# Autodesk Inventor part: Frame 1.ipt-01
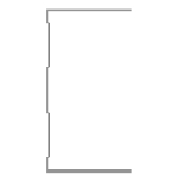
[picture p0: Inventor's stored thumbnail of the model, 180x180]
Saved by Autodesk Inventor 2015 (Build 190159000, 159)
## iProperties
_CCFamilyMember: 1
_CCFamilyDisplayName: Kévin - Kévin Novo
_FrameMemberDoc: Frame Member File
_Version: 15.0.0
_GetPNFromCC: 1
Created: 2015-04
Part Number: Frame 1.ipt-01
Material: Aluminum 6061
Description: Kévin Novo
Document SubType Name: Modeling
Standard: Kevin
Designer: suporte
Standards Organization: Kevin
Language: en-US
Size Designation: (Unnamed 1)
Categories: <MemberInstance><Categories><Category DisplayName="Structural Shapes" InternalName="089c4875-fa83-4c05-b084-43b9cc11f5ed" Mnemonic="GRDR"><CategoryParameter Dis
Density: 2.7 g/cm^3
Appearance: Aluminum - Flat
IsCustomPart: 1
G_L: 1275,000 mm
G_W: 50,000 mm
G_H: 75,000 mm
+97E5C577-A316-488B-9898-4BCBE5543E85+CUTDETAIL1: Cut
+B5E3F3FC-8DAF-4209-9454-317D479D3EF3+CUTDETAIL2: Cut
Author: suporte
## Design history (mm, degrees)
node "Start Plane"
node "End Plane"
sketch "Sketch"
  geometry: L1 (24.7, 37.5)-(24.7, 36.9); L2 (24.7, 36.9)-(-24.7, 36.9); L3 (-24.7, -36.9)-(24.7, -36.9); L4 (24.7, -36.9)-(24.7, -37.5); L5 (24.7, -37.5)-(-25.3, -37.5); L6 (-25.3, 37.5)-(24.7, 37.5); L7 (-24.7, 36.9)-(-24.7, 31.9); L8 (-24.7, 31.9)-(-23.3, 30.5); L9 (-23.3, 30.5)-(-23.3, 10.934); L10 (-23.3, 10.934)-(-24.7, 9.534); L11 (-24.7, 9.534)-(-24.7, -9.534); L12 (-24.7, -9.534)-(-23.3, -10.934); L13 (-23.3, -10.934)-(-23.3, -30.5); L14 (-23.3, -30.5)-(-24.7, -31.9); L15 (-24.7, -31.9)-(-24.7, -36.9); L16 (-25.3, -37.5)-(-25.3, -31.651); L17 (-25.3, -31.651)-(-23.9, -30.251); L18 (-23.9, -30.251)-(-23.9, -11.183); L19 (-23.9, -11.183)-(-25.3, -9.783); L20 (-25.3, -9.783)-(-25.3, 9.783); L21 (-25.3, 9.783)-(-23.9, 11.183); L22 (-23.9, 11.183)-(-23.9, 30.251); L23 (-23.9, 30.251)-(-25.3, 31.651); L24 (-25.3, 31.651)-(-25.3, 37.5); L25 (-25.3, 0)-(30.37, 0); 3 further points
  constraints: 50 end point, 10 point on line, 9 parallel, 5 perpendicular, 4 equal length, 3 midpoint, 3 vertical, 2 vertical alignment, 1 collinear, 1 horizontal, 1 horizontal alignment
  dimensions: "d3" = 0.6 distance of L1.start L1.end (= d6); "d5" = 75 distance between parallel lines of L5 L6; "d6" = 0.6 distance between parallel lines of L24 L7 (= d8); "d7" = 0.6 distance between parallel lines of L8 L23 (= d8); "d8" = 0.6 distance between parallel lines of L22 L9 (= d12); "Espessura" = 0.6 distance between parallel lines of L17 L14; "d10" = 0.6 distance between parallel lines of L13 L18 (= Espessura); "d11" = 0.6 distance between parallel lines of L12 L19 (= Espessura); "d12" = 0.6 distance between parallel lines of L21 L10 (= d11); "d13" = 5 distance of L2.end L7.end; "d15" = 135 deg angle of L9 L8; "d16" = 2 distance between parallel lines of L24 L9; "d17" = 50 distance of L6.start L1.start
extrude "Body" join sketch "Sketch" stored distance "d24" = 0.13; taper "d25" = 0 deg
node "Driven Length"
  sketch "Sketch10"
    geometry: L1 (0, 0)-(10, 0) reference
    constraints: 2 end point, 1 horizontal
  workplane "Work Plane7"
  sketch "Sketch11"
    geometry: L1 (-2, -87.5)-(12, -87.5) reference; L2 (-2, 1187.5)-(12, 1187.5) reference
    dimensions: "d27" = 1275 distance between parallel lines of L1 L2 (derived)
workplane "Work Plane8"
split "Split1"
workplane "Work Plane9"
split "Split2"
body "Solid1"
other parameters: "G_OFFSET_START" = 87.5 [user parameter; used in 1 equation term], "G_OFFSET_END" = -12.5 [user parameter; used in 1 equation term], "d22" = -87.5 (= -G_OFFSET_START), "d23" = 1187.5 (= tamanho + G_OFFSET_END), "G_L" = 1275 (= d27) [user parameter], "d34" = 90 deg
